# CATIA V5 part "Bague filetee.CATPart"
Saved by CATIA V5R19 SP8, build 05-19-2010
Part number: Bague filetee
Revision: ANY
Definition: UNKNOWN
Nomenclature: Bague filetée
Source: Unknown
Bounding box of the stored display mesh (mm): x -8.5 to 8.5, y -8.49 to 8.49, z 0 to 8
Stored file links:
  D:\Documents\1_Travail\1 - ac-limoges.fr\OneDrive - ac-limoges.fr\STI2D_Turgot\2 -2I2D\3_SEQUENCE_Serre_Connectée\3- Spécificités\ITEC\EC 3 Ouverture automatique\Simulation  Ouverture Automatique\Bague filetee.CATPart
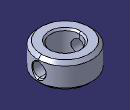
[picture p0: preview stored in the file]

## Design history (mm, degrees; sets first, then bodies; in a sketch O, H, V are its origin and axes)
Body1 "NONE" (main body)
  Solid1: solid without history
